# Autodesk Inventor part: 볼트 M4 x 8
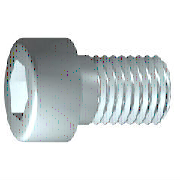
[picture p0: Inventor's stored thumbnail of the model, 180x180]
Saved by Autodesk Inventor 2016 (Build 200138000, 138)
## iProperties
IsCustomPart: 0
Created: 2012-02
Part Number: 볼트 M4 x 8
Material: 스테인리스강
Description: 6각 소켓 머리 캡 나사
Document SubType Name: Modeling
Standard: ISO 4762
Designer: mduedu
Standard Revision: Fourth edition 2004-03-01
Standards Organization: ISO
Language: ko-KR
Size Designation: M4 x 8
Categories: <MemberInstance><Categories><Category DisplayName="조임쇠" InternalName="e4da775c-781d-43d5-af7c-5136215cf5a6" Mnemonic="FSTN"><Category DisplayName="볼트" InternalN
Density: 8.08 g/cm^3
Mass: 1.89105 g
Surface Area: 2.80587 cm^2
Volume: 0.234041 cm^3
Appearance: 반광택
Author: mduedu
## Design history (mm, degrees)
sketch "스케치1"
  geometry: L1 (-1, 0)-(8, 0); L2 (8, 0)-(8, 2); L3 (8, 2)-(1.75, 2); L4 (1.75, 2)-(1.32, 2); L5 (1.32, 2)-(0, 2); L6 (0, 2)-(0, 3.5); L7 (0, 3.5)-(-4, 3.5); L8 (-4, 3.5)-(-4, 1.732); L9 (-4, 1.732)-(-2, 1.732); L10 (-2, 1.732)-(-1, 0); L11 (-6.4, 0)-(10.4, 0) reference; L12 (0, -0.7)-(0, 4.2) reference; L13 (1.75, 2)-(0, 2)
  constraints: 22 end point, 6 parallel, 2 collinear, 2 perpendicular, 1 horizontal, 1 point on line
  dimensions: "d1" = 6.25 distance from line of L3.end L2 (= GEL); "d2" = 0.42952 distance of L4.end L3.end (computed from GAL); "d3" = 4 distance between parallel lines of L8 L6 (= KOH); "d4" = 2 distance of L8.end L9.end (= INTI); "d5" = 60 deg angle of L10 L1; "d6" = 4 diameter of L3 L1 (= GD); "d7" = 4 diameter of L5 L1 (= BDM); "d8" = 3.4641 diameter of L9 L1 (= 1.1547 x SW); "d9" = 7 diameter of L7 L1 (= KOD); "d26" = 8 distance between parallel lines of L12 L2 (= NLG)
revolve "본체" sketch "스케치1" stored, may be unused: angle "d10" = 90 deg
sketch "스케치2"
  geometry: L1 (0, -4.9)-(0, 4.9) reference; L2 (-4.9, 0)-(4.9, 0) reference; L3 (1.732, 0)-(0.866, -1.5); L4 (0.866, -1.5)-(-0.866, -1.5); L5 (-0.866, -1.5)-(-1.732, 0); L6 (-1.732, 0)-(-0.866, 1.5); L7 (-0.866, 1.5)-(0.866, 1.5); L8 (0.866, 1.5)-(1.732, 0); 2 further points
  constraints: 12 end point, 1 coincident, 1 horizontal alignment, 1 point on line, 12 other
extrude "슬롯" join sketch "스케치2" stored distance "d11" = 10; taper "d12" = 0 deg
workplane "Work Plane1"
fillet "Fillet2" dims "d30" = 0.1 (= R)
body "Solid1"
fillet "모깎기1" dims "d17" = 0.4 (= RR)
feature "스레드" dims "d13" = 6.25 (= GEL), "d14" = 0
chamfer "모따기1" distance "d15" = 0.42941 (= -0.5 x SPD + 0.5 x GD); stored, may be unused: second distance "d16" = 0.42941 (= GUL), angle "d27" = 45 deg
other parameters: "GD" = 4 [user parameter; used in 2 equation terms], "NLG" = 8 [user parameter; used in 1 equation term], "GEL" = 6.25 [user parameter; used in 2 equation terms], "KOD" = 7 [user parameter; used in 1 equation term], "KOH" = 4 [user parameter; used in 1 equation term], "INTI" = 2 [user parameter; used in 1 equation term], "GAL" = 0.42941 (= 0.61345 x PTC) [user parameter; used in 1 equation term], "GUL" = 0.42941 (= 0.61345 x PTC) [user parameter; used in 1 equation term], "BDM" = 4 (= NND) [user parameter; used in 1 equation term], "SW" = 3 [user parameter; used in 2 equation terms], "RR" = 0.4 [user parameter; used in 1 equation term], "SPD" = 3.14117 (= NND - 1.2269 x PTC) [user parameter; used in 1 equation term], "d19" = 0, "d28" = 0, "d29" = 0, "R" = 0.1 [user parameter; used in 1 equation term], "TOA" = 30 deg [user parameter], "GD1" = 3.14117 (= THREADDIA - 1.2269 x PTC) [user parameter], "THREADDIA" = 4 [user parameter; used in 1 equation term], "FAWI" = 45 deg [user parameter], "TPU" = 14.28571 (computed from PTC) [user parameter], "PTC" = 0.7 [user parameter; used in 5 equation terms], "NND" = 4 [user parameter; used in 2 equation terms], "E0" = 3.465 (= 1.155 x SW) [user parameter]
